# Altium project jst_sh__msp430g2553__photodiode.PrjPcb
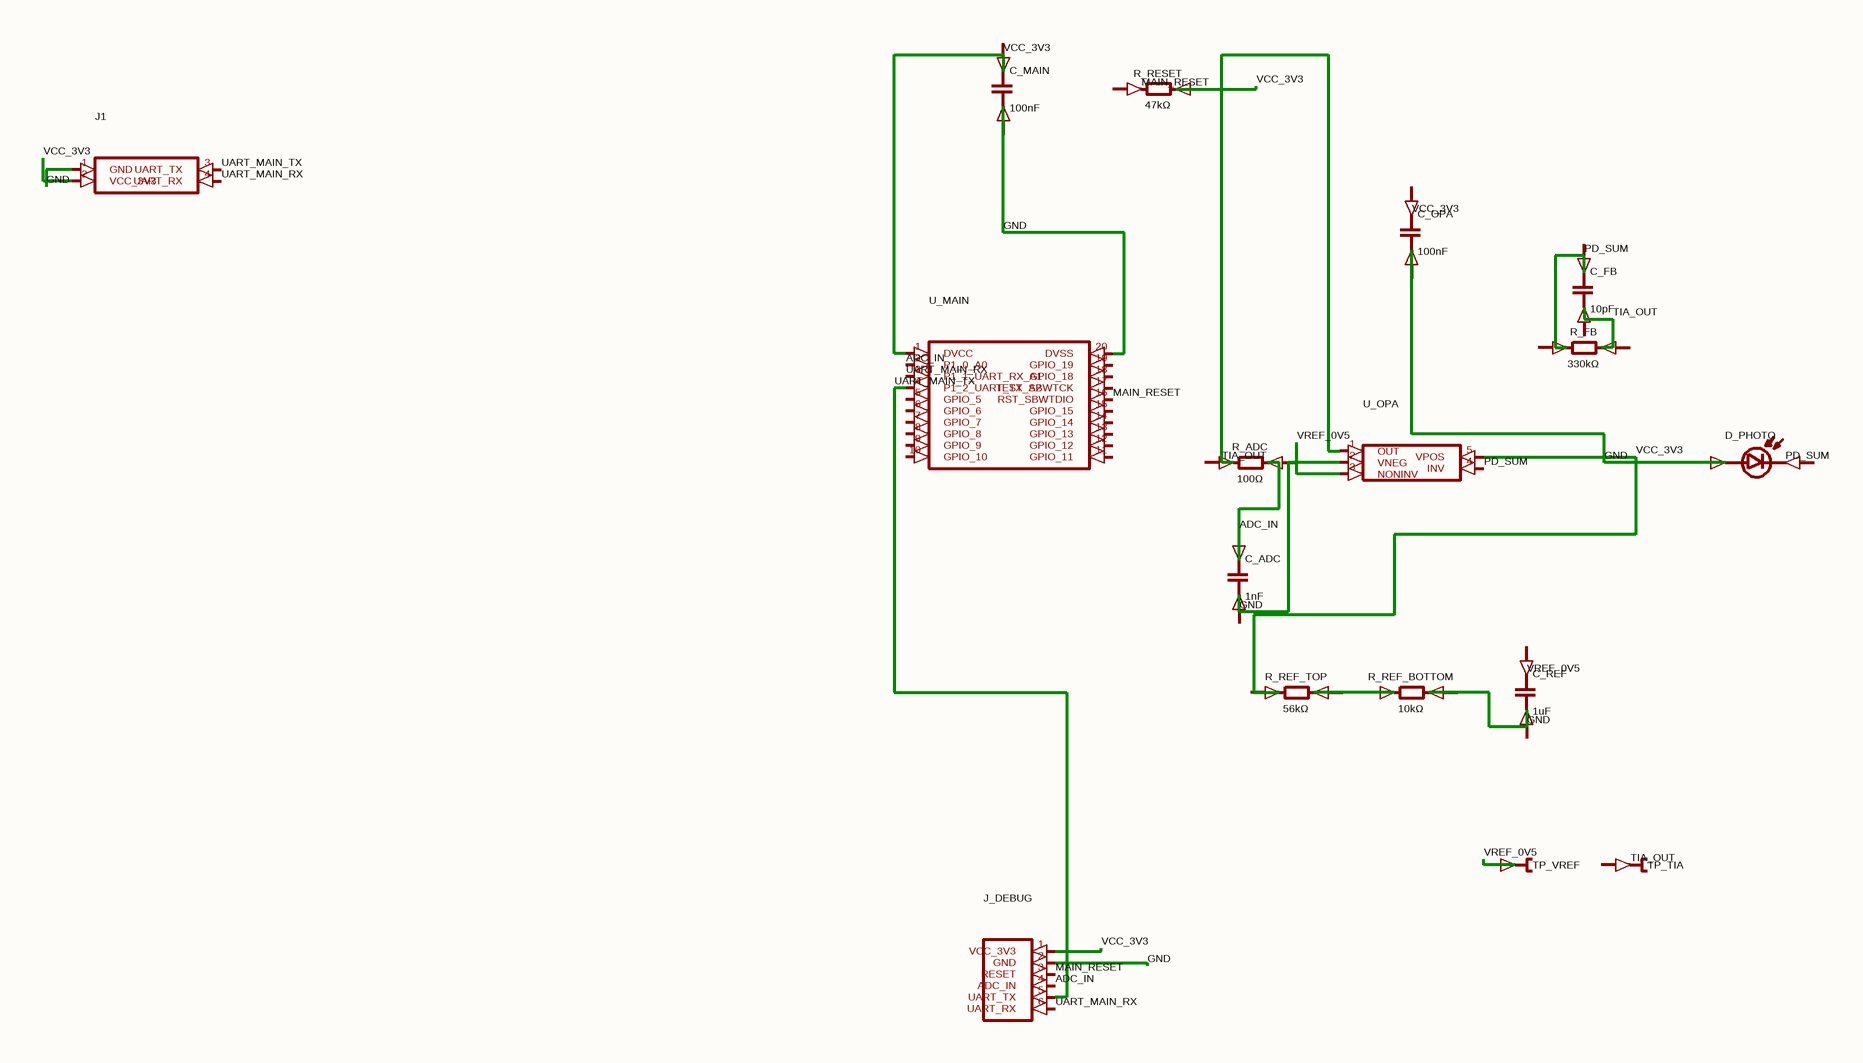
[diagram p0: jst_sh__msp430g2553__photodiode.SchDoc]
1 sheet, 17 parts. Net scope: global (net labels, ports and power ports of the same name join across sheets).
Board file: jst_sh__msp430g2553__photodiode.PcbDoc

## Sheet jst_sh__msp430g2553__photodiode.SchDoc
size 207 x 135 mm

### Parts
C_ADC  1nF
C_FB  10pF
C_MAIN  100nF
C_OPA  100nF
C_REF  1uF
D_PHOTO  (no value)
J1  (no value)
J_DEBUG  (no value)
R_ADC  100Ω
R_FB  330kΩ
R_REF_BOTTOM  10kΩ
R_REF_TOP  56kΩ
R_RESET  47kΩ
TP_TIA  (no value)
TP_VREF  (no value)
U_MAIN  (no value)
U_OPA  (no value)

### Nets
ADC_IN: C_ADC.1(anode) J_DEBUG.4(ADC_IN) U_MAIN.2(P1_0_A0)
GND: C_MAIN.2(cathode) C_OPA.2(cathode) D_PHOTO.1(anode) J1.1(GND) J1.2(VCC_3V3) J1.3(UART_TX) J_DEBUG.1(VCC_3V3) J_DEBUG.2(GND) J_DEBUG.5(UART_TX) R_ADC.2(cathode) R_REF_BOTTOM.2(cathode) R_RESET.2(cathode) TP_VREF.1(pin1) U_MAIN.1(DVCC) U_MAIN.4(P1_2_UART_TX_A2) U_MAIN.20(DVSS) U_OPA.1(OUT) U_OPA.2(VNEG) U_OPA.3(NONINV) U_OPA.5(VPOS)  [also labelled TIA_OUT, UART_MAIN_TX, VCC_3V3, VREF_0V5]
MAIN_RESET: J_DEBUG.3(RESET) U_MAIN.16(RST_SBWTDIO)
PD_SUM: U_OPA.4(INV)
UART_MAIN_RX: J1.4(UART_RX) J_DEBUG.6(UART_RX) U_MAIN.3(P1_1_UART_RX_A1)
NetR_REF_BOTTOM_1: R_REF_BOTTOM.1(anode) R_REF_TOP.2(cathode)

Not connected (* = marked no-connect by the designer): C_ADC 2(cathode); C_FB 1(anode) 2(cathode); C_MAIN 1(anode); C_OPA 1(anode); C_REF 1(anode) 2(cathode); D_PHOTO 2(cathode); R_ADC 1(anode); R_FB 1(anode) 2(cathode); R_REF_TOP 1(anode); R_RESET 1(anode); TP_TIA 1(pin1); U_MAIN 5(GPIO_5) 6(GPIO_6) 7(GPIO_7) 8(GPIO_8) 9(GPIO_9) 10(GPIO_10) 11(GPIO_11) 12(GPIO_12) 13(GPIO_13) 14(GPIO_14) 15(GPIO_15) 17(TEST_SBWTCK) 18(GPIO_18) 19(GPIO_19)

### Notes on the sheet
- Labels drawn without touching a wire or pin: MAIN_RESET, PD_SUM, TIA_OUT, VCC_3V3, VREF_0V5

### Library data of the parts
C_ADC C_FB C_MAIN C_OPA C_REF = capacitor_down
D_PHOTO = photodiode_horz
J1 = J1
J_DEBUG = J_DEBUG
R_ADC R_FB R_REF_BOTTOM R_REF_TOP R_RESET = boxresistor_right
TP_TIA TP_VREF = testpoint_right
U_MAIN = U_MAIN
U_OPA = U_OPA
